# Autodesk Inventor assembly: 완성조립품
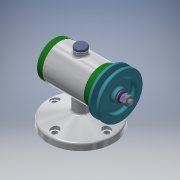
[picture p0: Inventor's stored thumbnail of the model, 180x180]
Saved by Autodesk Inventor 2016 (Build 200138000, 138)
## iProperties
Created: 2018-12
Part Number: 완성조립품
Material: 일반
Document SubType Name: Assembly
Designer: 605-17
Author: 605-17
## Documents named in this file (15)
- C:\Users\605-17\Desktop\481207V1029\답안조립품.iam
- C:\Users\605-17\Desktop\481207V1029\V벨트풀리.ipt
- C:\Users\605-17\Desktop\481207V1029\고무캡.ipt
- C:\Users\605-17\Desktop\481207V1029\너트 M8.ipt
- 너트 M8.ipt
- C:\Users\605-17\Desktop\481207V1029\뒤커버.ipt
- C:\Users\605-17\Desktop\481207V1029\베어링 15 x 32 x 9.ipt
- C:\Users\605-17\Desktop\481207V1029\본체.ipt
- C:\Users\605-17\Desktop\481207V1029\볼트 M4 x 12.ipt
- C:\Users\605-17\Desktop\481207V1029\스프링와셔 8.ipt
- C:\Users\605-17\Desktop\481207V1029\앞커버.ipt
- C:\Users\605-17\Desktop\481207V1029\오일 실 15 25 7.ipt
- C:\Users\605-17\Desktop\481207V1029\와셔 8x17.ipt
- C:\Users\605-17\Desktop\481207V1029\축.ipt
- C:\Users\605-17\Desktop\481207V1029\키 3 x 3 x 12.ipt
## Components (2 placed, 2 different names)
1. V벨트풀리:1
2. 고무캡:1 — 각도:3
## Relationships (1: Angle 1)
- 각도:3 [Angle]: 고무캡:1
